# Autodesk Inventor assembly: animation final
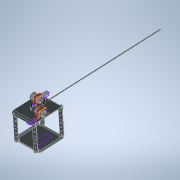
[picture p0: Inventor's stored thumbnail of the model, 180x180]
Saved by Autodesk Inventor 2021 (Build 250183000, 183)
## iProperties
Created: 2021-07
Part Number: animation final
Document SubType Name: Assembly
Designer: user
Author: user
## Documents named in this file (7)
- C:\Users\user\Downloads\animation final.iam
- C:\Users\user\Downloads\complete.iam
- C:\Users\user\Downloads\god.iam
- C:\Users\user\Downloads\wwe.ipt
- C:\Users\user\Downloads\animation nut.ipt
- C:\Users\user\Downloads\bolt  stdui.ipt
- C:\Users\user\Downloads\8523641.ipt
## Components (14 placed, 6 different names)
1. complete:1 [sub-assembly] — Flush:1, Tangent:1, Tangent:2, Flush:2, Rigid:1, Rigid:2, Rigid:3, Rigid:4, Mate:1, Mate:2
2. god:1 [sub-assembly] — Flush:1, Tangent:1, Tangent:2, Tangent:3, Tangent:4, Flush:3, Flush:4
3. wwe:1 — Flush:2, Tangent:3, Rotational:2, Rotational:4
4. wwe:2 — Tangent:4, Flush:3, Rotational:1, Rotational:3
5. animation nut:1 — Rotational:2
6. animation nut:2 — Rotational:3
7. animation nut:3 — Rotational:1
8. animation nut:4 — Rotational:4
9. bolt  stdui:1 — Rigid:2
10. bolt  stdui:2 — Rigid:3
11. bolt  stdui:3 — Rigid:1
12. bolt  stdui:4 — Rigid:4
13. 8523641:1 — Mate:2
14. 8523641:2 — Mate:1, Flush:4
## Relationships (18: Flush 4, Tangent 4, RevoluteJoint 4, WeldJoint 4, Mate 2)
- Flush:1: complete:1 ↔ god:1
- Tangent:1: complete:1 ↔ god:1
- Tangent:2: complete:1 ↔ god:1
- Flush:2: complete:1 ↔ wwe:1
- Tangent:3: god:1 ↔ wwe:1
- Tangent:4: god:1 ↔ wwe:2
- Flush:3: god:1 ↔ wwe:2
- Rotational:1 [RevoluteJoint]: wwe:2 ↔ animation nut:3
- Rotational:2 [RevoluteJoint]: wwe:1 ↔ animation nut:1
- Rotational:3 [RevoluteJoint]: wwe:2 ↔ animation nut:2
- Rotational:4 [RevoluteJoint]: wwe:1 ↔ animation nut:4
- Rigid:1 [WeldJoint]: complete:1 ↔ bolt  stdui:3
- Rigid:2 [WeldJoint]: complete:1 ↔ bolt  stdui:1
- Rigid:3 [WeldJoint]: complete:1 ↔ bolt  stdui:2
- Rigid:4 [WeldJoint]: complete:1 ↔ bolt  stdui:4
- Mate:1: complete:1 ↔ 8523641:2
- Flush:4: god:1 ↔ 8523641:2
- Mate:2: complete:1 ↔ 8523641:1
